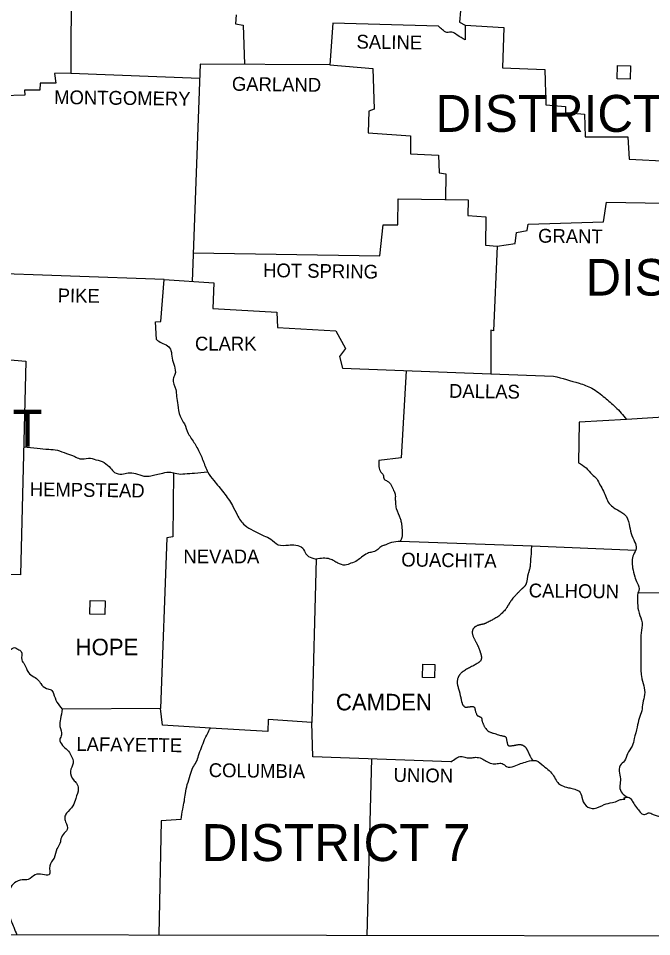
# Model space of a CAD drawing. Extents: x -0.25 to 1.42, y 0 to 0.92.
# Drawn here: x 1.1381 to 1.2274, y 0.5736 to 0.703 of the extents above; entities that cross this region are included whole.
import ezdxf

# ---------------------------------------------------------------- set-up
doc = ezdxf.new("R2010")
doc.units = 0
doc.layers.add('SHET_Annotations', color=7, linetype='Continuous')

msp = doc.modelspace()

# ---------------------------------------------------------------- linework, layer by layer
at = {"layer": 'SHET_Annotations'}
for points in [[(1.17039, 0.73425), (1.17018, 0.72769), (1.15981, 0.72764), (1.15844, 0.72647), (1.15763, 0.72466), (1.15652, 0.72471), (1.15647, 0.7237), (1.15514, 0.72354), (1.15519, 0.72261), (1.14858, 0.72277), (1.14832, 0.72204), (1.1456, 0.72194), (1.14552, 0.69525), (1.14321, 0.6952), (1.14342, 0.69385), (1.14122, 0.69387), (1.14116, 0.69286), (1.13901, 0.69286), (1.13906, 0.69216), (1.1359, 0.69206), (1.13582, 0.68928), (1.13274, 0.68957), (1.13222, 0.66711)], [(1.21552, 0.70884), (1.21225, 0.70923), (1.21238, 0.70798), (1.20639, 0.70775), (1.20621, 0.70599), (1.20058, 0.70567), (1.20027, 0.70246), (1.2011, 0.70204), (1.2011, 0.69994)], [(1.16881, 0.70347), (1.16873, 0.70223), (1.1698, 0.70204), (1.16999, 0.69651)], [(1.19734, 0.70186), (1.18245, 0.7023), (1.18204, 0.69644), (1.16375, 0.69655), (1.16263, 0.66592)], [(1.2011, 0.70204), (1.20654, 0.70171), (1.20634, 0.696), (1.2123, 0.69577), (1.21243, 0.69079), (1.21523, 0.69056), (1.21523, 0.6897), (1.2179, 0.68949), (1.21798, 0.6863), (1.224, 0.6863), (1.22421, 0.68314), (1.22976, 0.68288), (1.22973, 0.67694)], [(1.18204, 0.69644), (1.18808, 0.69592), (1.18826, 0.69017), (1.18751, 0.68993), (1.18741, 0.68687), (1.19337, 0.68643), (1.19337, 0.68392), (1.19734, 0.68371), (1.19742, 0.68122), (1.19835, 0.68106), (1.19832, 0.67745)], [(1.14552, 0.69525), (1.16368, 0.69454)], [(1.16278, 0.66994), (1.18904, 0.66955), (1.18953, 0.67391), (1.19161, 0.67388), (1.19166, 0.67754), (1.20149, 0.67741), (1.20144, 0.6752), (1.20398, 0.67502), (1.20395, 0.67103), (1.20561, 0.67087)], [(1.20561, 0.67087), (1.20815, 0.67126), (1.20833, 0.67282), (1.20984, 0.67308), (1.20994, 0.67398), (1.22057, 0.67432), (1.22099, 0.67707), (1.23188, 0.67691)], [(1.20561, 0.67087), (1.20507, 0.65894), (1.20468, 0.65907), (1.2047, 0.65291)], [(1.15867, 0.6662), (1.13222, 0.66711), (1.11466, 0.66714), (1.11427, 0.66192), (1.11489, 0.66148), (1.11487, 0.65562), (1.10171, 0.65622)], [(1.13222, 0.66711), (1.13222, 0.66104), (1.13323, 0.66086), (1.13312, 0.65521), (1.13919, 0.65471), (1.13844, 0.62458), (1.12604, 0.62486)], [(1.15758, 0.65772), (1.15745, 0.66024), (1.1582, 0.66029), (1.15867, 0.6662), (1.16567, 0.66571), (1.16552, 0.66211), (1.17457, 0.66161), (1.17465, 0.65943), (1.18284, 0.65894), (1.18424, 0.65648), (1.18339, 0.65536), (1.1838, 0.65368), (1.2047, 0.65291)], [(1.19278, 0.65335), (1.19205, 0.64107), (1.18894, 0.64071)], [(1.2047, 0.65291), (1.21355, 0.65259)], [(1.23046, 0.64688), (1.22382, 0.64648)], [(1.22382, 0.64648), (1.21713, 0.64608), (1.21707, 0.64037)], [(1.15999, 0.63897), (1.15989, 0.62992), (1.15906, 0.62982), (1.15815, 0.60578)], [(1.19194, 0.62934), (1.21051, 0.62865), (1.22514, 0.62808)], [(1.18009, 0.62681), (1.1795, 0.60378), (1.17335, 0.60422), (1.1733, 0.60253), (1.16519, 0.603)], [(1.2254, 0.62206), (1.24604, 0.62211)], [(1.12566, 0.61083), (1.12576, 0.5739), (1.29301, 0.57362)], [(1.16519, 0.603), (1.15846, 0.60339), (1.15815, 0.60578), (1.14433, 0.60565)], [(1.19908, 0.59823), (1.17962, 0.59896), (1.1795, 0.60378)], [(1.1879, 0.59865), (1.18721, 0.5738)], [(1.16106, 0.59011), (1.15825, 0.58993), (1.15795, 0.57385)]]:
    msp.add_lwpolyline(points, dxfattribs=at)
for points in [[(1.22249, 0.69447), (1.22255, 0.69636), (1.22439, 0.69631), (1.22434, 0.69442)], [(1.14822, 0.61903), (1.14827, 0.62097), (1.15037, 0.62092), (1.15032, 0.61898)], [(1.19506, 0.61011), (1.19511, 0.612), (1.19679, 0.61195), (1.19674, 0.61006)]]:
    msp.add_lwpolyline(points, close=True, dxfattribs=at)
for points in [[(1.2011, 0.69994), (1.19993, 0.70064), (1.19921, 0.70103), (1.1985, 0.70101), (1.19791, 0.70137), (1.19734, 0.70186)], [(1.15758, 0.65772), (1.15828, 0.65728), (1.15916, 0.65687), (1.15963, 0.65619), (1.15979, 0.65513), (1.16012, 0.65399), (1.1602, 0.65282), (1.15994, 0.65217), (1.1603, 0.65072), (1.16043, 0.64971), (1.16059, 0.64854), (1.16093, 0.64693), (1.16152, 0.64584), (1.16207, 0.64452), (1.16298, 0.64307), (1.16378, 0.64154), (1.16414, 0.64074), (1.16482, 0.63905), (1.16567, 0.63788), (1.16707, 0.63615), (1.16829, 0.63436), (1.16897, 0.63303), (1.17003, 0.63158), (1.17122, 0.63085), (1.17273, 0.6301), (1.17369, 0.62961), (1.17475, 0.62883), (1.17618, 0.62878), (1.17721, 0.62878), (1.1782, 0.62834), (1.17864, 0.62753), (1.17947, 0.62696), (1.18009, 0.62681)], [(1.21355, 0.65259), (1.21713, 0.65158), (1.21894, 0.65088), (1.22076, 0.64955), (1.22226, 0.64823), (1.22382, 0.64648)], [(1.13889, 0.6426), (1.1408, 0.64245), (1.14241, 0.64227), (1.14363, 0.64214), (1.1449, 0.64169), (1.14607, 0.64128), (1.14679, 0.64094), (1.14801, 0.64102), (1.14907, 0.64081), (1.15024, 0.6404), (1.15112, 0.63962), (1.15169, 0.63902), (1.15273, 0.63879), (1.15361, 0.63895), (1.15465, 0.63884), (1.15582, 0.63851), (1.1568, 0.63853), (1.15758, 0.63871), (1.15849, 0.63892), (1.1596, 0.63905), (1.16046, 0.63884), (1.1616, 0.63882), (1.16295, 0.63892), (1.16478, 0.63912)], [(1.18894, 0.64071), (1.18894, 0.63985), (1.18922, 0.63905), (1.18953, 0.63869), (1.18969, 0.63806), (1.1901, 0.6378), (1.19067, 0.63723), (1.19101, 0.63648), (1.19122, 0.63596), (1.19124, 0.63532), (1.19127, 0.63469), (1.19137, 0.63394), (1.19192, 0.63254), (1.19207, 0.632), (1.19215, 0.63153), (1.1922, 0.63075), (1.19218, 0.62984), (1.19194, 0.62934)], [(1.21707, 0.64037), (1.21811, 0.63967), (1.21897, 0.63874), (1.21962, 0.63809), (1.22006, 0.63729), (1.22057, 0.63638), (1.22138, 0.63464), (1.22205, 0.63404), (1.22301, 0.63345), (1.22358, 0.63306), (1.22418, 0.63174), (1.22447, 0.63041), (1.22496, 0.62922), (1.22519, 0.62831), (1.22478, 0.62741), (1.22467, 0.62559), (1.22498, 0.62432), (1.22532, 0.62344), (1.22555, 0.62237), (1.2254, 0.62206)], [(1.18969, 0.62875), (1.18922, 0.62855), (1.18865, 0.62805), (1.18795, 0.62779), (1.18733, 0.62761), (1.18647, 0.62707), (1.18587, 0.6266), (1.18499, 0.62621), (1.18416, 0.62595), (1.18315, 0.62624), (1.18261, 0.62655), (1.18204, 0.62681), (1.18009, 0.62681)], [(1.18969, 0.62875), (1.19075, 0.62919), (1.19194, 0.62934)], [(1.2254, 0.62206), (1.22558, 0.61921), (1.226, 0.61784), (1.22589, 0.61641), (1.22581, 0.61498), (1.22584, 0.61371), (1.22581, 0.61247), (1.22584, 0.6112), (1.22592, 0.61029), (1.22625, 0.60897), (1.22636, 0.60772), (1.2261, 0.60653), (1.22597, 0.60544), (1.22561, 0.60435), (1.2253, 0.60313), (1.22491, 0.60152), (1.22459, 0.60046), (1.22395, 0.59937), (1.22353, 0.59838), (1.22291, 0.59774), (1.22283, 0.59665), (1.22296, 0.59561), (1.22286, 0.5947), (1.22319, 0.59385), (1.224, 0.59325)], [(1.12566, 0.61083), (1.12724, 0.61151), (1.12796, 0.6113), (1.12853, 0.6107), (1.12923, 0.61068), (1.1296, 0.61122), (1.13027, 0.6113), (1.13082, 0.61125), (1.13141, 0.61159), (1.13191, 0.61182), (1.13258, 0.61205), (1.1331, 0.61226), (1.13354, 0.61275), (1.1344, 0.61314), (1.13533, 0.61348), (1.13559, 0.61395), (1.13606, 0.61413), (1.13696, 0.61407), (1.13759, 0.61433), (1.13808, 0.6141), (1.13852, 0.61379), (1.13862, 0.61262), (1.13899, 0.61197), (1.13956, 0.61083), (1.14031, 0.61024), (1.14103, 0.60964), (1.14129, 0.60928), (1.1421, 0.60858), (1.14277, 0.60837), (1.14308, 0.60788), (1.14358, 0.60666), (1.14433, 0.60565)], [(1.14433, 0.60565), (1.14407, 0.6043), (1.14399, 0.60323), (1.14422, 0.60204), (1.14399, 0.60142), (1.14435, 0.60056), (1.14505, 0.59989), (1.14555, 0.59916), (1.14586, 0.59807), (1.14547, 0.59691), (1.14591, 0.59569), (1.14633, 0.59522), (1.14658, 0.59447), (1.14622, 0.59309), (1.14583, 0.59203), (1.14492, 0.59099), (1.14467, 0.59047), (1.1448, 0.5898), (1.14503, 0.58871), (1.14477, 0.58837), (1.1442, 0.5876), (1.14399, 0.58674), (1.14358, 0.58599), (1.14316, 0.58469), (1.14256, 0.58358), (1.14246, 0.58233), (1.14153, 0.58236), (1.14052, 0.58233), (1.13953, 0.58168), (1.13867, 0.58163), (1.13761, 0.58119), (1.13696, 0.58033), (1.13676, 0.57937), (1.13647, 0.57847), (1.13673, 0.57691), (1.13714, 0.57582), (1.13748, 0.57494), (1.13792, 0.57388)], [(1.16106, 0.59011), (1.16129, 0.59156), (1.16152, 0.59273), (1.16168, 0.59379), (1.16194, 0.59504), (1.16235, 0.59636), (1.16272, 0.59745), (1.16321, 0.59823), (1.16352, 0.59914), (1.16393, 0.60025), (1.16438, 0.60137), (1.16519, 0.603)], [(1.19908, 0.59823), (1.19983, 0.59875), (1.2005, 0.59901), (1.2012, 0.59885), (1.2019, 0.5988), (1.20255, 0.59888), (1.20338, 0.59872), (1.20405, 0.59833), (1.20483, 0.598), (1.20561, 0.598), (1.20629, 0.598), (1.20691, 0.59758), (1.20797, 0.59763), (1.2089, 0.598), (1.20981, 0.59828), (1.21106, 0.59841), (1.21212, 0.59766), (1.21292, 0.59701), (1.21355, 0.59628), (1.21401, 0.59545), (1.21453, 0.59499), (1.21534, 0.59468), (1.21598, 0.59452), (1.21674, 0.59431), (1.21715, 0.59411), (1.21751, 0.59328), (1.21811, 0.59206), (1.21928, 0.59167), (1.22065, 0.59221), (1.22182, 0.59252), (1.22265, 0.59278), (1.22312, 0.59296), (1.22358, 0.59304), (1.22348, 0.59312), (1.224, 0.59325), (1.22452, 0.59289), (1.22483, 0.59239), (1.22537, 0.59164), (1.22587, 0.59102), (1.22636, 0.59081), (1.2269, 0.59107), (1.22755, 0.59084), (1.22815, 0.59063), (1.22885, 0.59042), (1.22942, 0.5904), (1.23022, 0.59022), (1.23079, 0.58988), (1.23134, 0.58954), (1.23191, 0.58897), (1.23245, 0.58804), (1.23263, 0.58731), (1.23326, 0.58658), (1.23388, 0.58658), (1.23471, 0.58542), (1.23505, 0.58495), (1.23572, 0.58415), (1.23621, 0.58412), (1.2372, 0.58397)]]:
    msp.add_spline(points, degree=3, dxfattribs=at)
msp.add_open_spline([(1.21045, 0.62865), (1.21038, 0.62772), (1.2103, 0.62678), (1.21023, 0.62585), (1.21021, 0.62561), (1.21015, 0.62538), (1.21009, 0.62514), (1.21005, 0.62503), (1.21002, 0.62491), (1.20998, 0.6248), (1.20995, 0.62468), (1.20992, 0.62457), (1.20989, 0.62445), (1.20984, 0.62423), (1.20982, 0.62401), (1.20978, 0.62379), (1.20976, 0.62368), (1.20974, 0.62357), (1.20971, 0.62346), (1.20969, 0.62341), (1.20967, 0.62336), (1.20965, 0.62331), (1.20964, 0.62328), (1.20963, 0.62325), (1.20962, 0.62323), (1.20961, 0.6232), (1.20959, 0.62318), (1.20958, 0.62315), (1.20954, 0.62308), (1.20949, 0.62301), (1.20943, 0.62294), (1.20937, 0.62288), (1.20931, 0.62282), (1.20925, 0.62277), (1.20919, 0.62271), (1.20912, 0.62266), (1.20906, 0.6226), (1.209, 0.62254), (1.20894, 0.62249), (1.20888, 0.62243), (1.20876, 0.6223), (1.20864, 0.62218), (1.20852, 0.62205), (1.20839, 0.62192), (1.20827, 0.6218), (1.20815, 0.62167), (1.20791, 0.62143), (1.20771, 0.62115), (1.2075, 0.62087), (1.20745, 0.62079), (1.20739, 0.62071), (1.20734, 0.62063), (1.20729, 0.62054), (1.20724, 0.62046), (1.20719, 0.62038), (1.20714, 0.62029), (1.20709, 0.62021), (1.20704, 0.62013), (1.20699, 0.62004), (1.20694, 0.61996), (1.20688, 0.61988), (1.20671, 0.61964), (1.2065, 0.61942), (1.20629, 0.61921), (1.20605, 0.61898), (1.20581, 0.61876), (1.20553, 0.61859), (1.20527, 0.61843), (1.205, 0.61829), (1.20473, 0.61815), (1.20445, 0.618), (1.20418, 0.61786), (1.2039, 0.61773), (1.20382, 0.6177), (1.20374, 0.61767), (1.20366, 0.61765), (1.20358, 0.61763), (1.2035, 0.61761), (1.20341, 0.61759), (1.20333, 0.61758), (1.20325, 0.61756), (1.20316, 0.61754), (1.20308, 0.61753), (1.203, 0.6175), (1.20291, 0.61747), (1.20278, 0.61743), (1.20266, 0.61737), (1.20254, 0.61729), (1.20248, 0.61726), (1.20243, 0.61722), (1.20238, 0.61717), (1.20236, 0.61714), (1.20233, 0.61712), (1.20231, 0.61709), (1.20228, 0.61706), (1.20226, 0.61704), (1.20224, 0.61701), (1.20218, 0.61692), (1.20215, 0.61683), (1.20212, 0.61674), (1.20209, 0.61664), (1.20208, 0.61654), (1.20208, 0.61645), (1.2021, 0.61626), (1.20214, 0.61607), (1.20221, 0.61589), (1.20227, 0.61576), (1.20233, 0.61563), (1.20239, 0.61551), (1.20246, 0.61538), (1.20253, 0.61526), (1.20259, 0.61513), (1.20266, 0.615), (1.20273, 0.61488), (1.20279, 0.61475), (1.20286, 0.61462), (1.20291, 0.61449), (1.20297, 0.61436), (1.20306, 0.61412), (1.20314, 0.61388), (1.20322, 0.61363), (1.20325, 0.61356), (1.20327, 0.61349), (1.20329, 0.61341), (1.20331, 0.61334), (1.20333, 0.61326), (1.20334, 0.61318), (1.20336, 0.61311), (1.20337, 0.61303), (1.20337, 0.61295), (1.20337, 0.61291), (1.20337, 0.61288), (1.20337, 0.61284), (1.20337, 0.6128), (1.20336, 0.61276), (1.20335, 0.61273), (1.20334, 0.61263), (1.20329, 0.61253), (1.20323, 0.61245), (1.20316, 0.61236), (1.20308, 0.61229), (1.20299, 0.61223), (1.20276, 0.61209), (1.20253, 0.61195), (1.20229, 0.61182), (1.202, 0.61166), (1.2017, 0.61151), (1.20141, 0.61135), (1.20115, 0.61121), (1.2009, 0.61104), (1.20066, 0.61086), (1.20053, 0.61076), (1.20042, 0.61065), (1.20032, 0.61052), (1.20027, 0.61046), (1.20023, 0.6104), (1.20019, 0.61033), (1.20015, 0.61026), (1.20012, 0.61018), (1.20009, 0.61011), (1.20002, 0.60993), (1.19998, 0.60975), (1.19997, 0.60957), (1.19996, 0.6094), (1.19997, 0.60922), (1.20001, 0.60904), (1.20003, 0.60894), (1.20006, 0.60884), (1.20009, 0.60874), (1.20012, 0.60864), (1.20015, 0.60854), (1.20018, 0.60843), (1.20021, 0.60833), (1.20024, 0.60823), (1.20027, 0.60813), (1.2003, 0.60803), (1.20032, 0.60793), (1.20035, 0.60782), (1.2004, 0.60758), (1.20045, 0.60732), (1.2005, 0.60707), (1.20053, 0.60697), (1.20055, 0.60686), (1.20058, 0.60675), (1.2006, 0.60664), (1.20064, 0.60654), (1.20068, 0.60643), (1.20072, 0.60633), (1.20077, 0.60624), (1.20084, 0.60616), (1.20088, 0.60611), (1.20091, 0.60608), (1.20096, 0.60604), (1.20098, 0.60603), (1.201, 0.60601), (1.20102, 0.606), (1.20105, 0.60598), (1.20107, 0.60597), (1.2011, 0.60596), (1.20113, 0.60594), (1.20117, 0.60593), (1.20121, 0.60593), (1.20125, 0.60593), (1.20128, 0.60594), (1.20132, 0.60595), (1.20136, 0.60595), (1.20139, 0.60596), (1.20143, 0.60597), (1.20147, 0.60598), (1.2015, 0.60598), (1.20154, 0.60598), (1.20157, 0.60599), (1.20161, 0.60599), (1.20164, 0.60599), (1.20168, 0.606), (1.20171, 0.606), (1.20175, 0.60601), (1.20182, 0.60602), (1.20189, 0.60603), (1.20195, 0.60604), (1.20202, 0.60605), (1.20209, 0.60605), (1.20216, 0.60603), (1.2022, 0.60603), (1.20223, 0.60602), (1.20227, 0.606), (1.20228, 0.60599), (1.2023, 0.60598), (1.20232, 0.60597), (1.20234, 0.60596), (1.20235, 0.60595), (1.20237, 0.60593), (1.2024, 0.6059), (1.20242, 0.60586), (1.20243, 0.60582), (1.20244, 0.60578), (1.20244, 0.60574), (1.20245, 0.6057), (1.20246, 0.60563), (1.20248, 0.60556), (1.2025, 0.60549), (1.20255, 0.60529), (1.20262, 0.60509), (1.20271, 0.60489), (1.20273, 0.60483), (1.20278, 0.60477), (1.20284, 0.60474), (1.20291, 0.60471), (1.20298, 0.60468), (1.20304, 0.60465), (1.20311, 0.60461), (1.20318, 0.60458), (1.20324, 0.60455), (1.2033, 0.60452), (1.20335, 0.60446), (1.20338, 0.6044), (1.2034, 0.60436), (1.20341, 0.60433), (1.20342, 0.60429), (1.20342, 0.60425), (1.20343, 0.60421), (1.20343, 0.60417), (1.20344, 0.60413), (1.20345, 0.60409), (1.20345, 0.60405), (1.20346, 0.60401), (1.20347, 0.60397), (1.20348, 0.60393), (1.20354, 0.60378), (1.2036, 0.60363), (1.20366, 0.60349), (1.20373, 0.60333), (1.20381, 0.60319), (1.2039, 0.60305), (1.20406, 0.6028), (1.20427, 0.60257), (1.20455, 0.60246), (1.20472, 0.60238), (1.20489, 0.60233), (1.20507, 0.60227), (1.20541, 0.60217), (1.20576, 0.60206), (1.2061, 0.60196), (1.20628, 0.60191), (1.20647, 0.60188), (1.20665, 0.60183), (1.20668, 0.60183), (1.2067, 0.60182), (1.20673, 0.6018), (1.2068, 0.60174), (1.20686, 0.60166), (1.20688, 0.60158), (1.2069, 0.60143), (1.20693, 0.60128), (1.20696, 0.60114), (1.20698, 0.601), (1.20701, 0.60086), (1.20704, 0.60072), (1.20705, 0.60066), (1.20708, 0.60062), (1.20713, 0.60057), (1.20717, 0.60054), (1.20722, 0.60052), (1.20727, 0.60051), (1.20739, 0.6005), (1.20751, 0.6005), (1.20763, 0.60052), (1.20775, 0.60053), (1.20788, 0.60054), (1.208, 0.60056), (1.20808, 0.60058), (1.20817, 0.6006), (1.20826, 0.60062), (1.20834, 0.60064), (1.20843, 0.60065), (1.20852, 0.60067), (1.20867, 0.60069), (1.20883, 0.60068), (1.20899, 0.60065), (1.20907, 0.60063), (1.20914, 0.60061), (1.20922, 0.60057), (1.20926, 0.60055), (1.2093, 0.60053), (1.20933, 0.60051), (1.20937, 0.60049), (1.20941, 0.60046), (1.20945, 0.60043), (1.20954, 0.60036), (1.20962, 0.60028), (1.20968, 0.60018), (1.20974, 0.60008), (1.20979, 0.59999), (1.20984, 0.59989), (1.20988, 0.59981), (1.20992, 0.59974), (1.20995, 0.59966), (1.20999, 0.59958), (1.21002, 0.5995), (1.21006, 0.59942), (1.21009, 0.59934), (1.21013, 0.59927), (1.21016, 0.59919), (1.2102, 0.59911), (1.21024, 0.59903), (1.21028, 0.59896), (1.21037, 0.59879), (1.21044, 0.59862), (1.21056, 0.59848)], degree=3, dxfattribs=at)

# ---------------------------------------------------------------- texts
for s, rotation, p in [('SALINE', 359.1885, (1.18576, 0.69873)), ('GARLAND', 359.2717, (1.16821, 0.69279)), ('MONTGOMERY', 359.2707, (1.14317, 0.69092)), ('GRANT', 359.3139, (1.21135, 0.67139)), ('HOT SPRING', 359.1956, (1.17261, 0.66654)), ('PIKE', 359.1737, (1.14367, 0.66299)), ('DALLAS', 359.2802, (1.1988, 0.64953)), ('HEMPSTEAD', 359.2571, (1.13973, 0.63568)), ('OUACHITA', 359.2027, (1.19207, 0.62577)), ('CALHOUN', 359.2686, (1.21003, 0.62142)), ('LAFAYETTE', 359.2511, (1.1463, 0.59979)), ('COLUMBIA', 359.2105, (1.16495, 0.59611)), ('UNION', 359.2015, (1.19099, 0.59543))]:
    msp.add_text(s, height=0.001945, rotation=rotation, dxfattribs=at).set_placement(p)
for s, height, p in [('DISTRICT 6', 0.005203, (1.1969, 0.68699)), ('DISTRICT 2', 0.005157, (1.21806, 0.66393)), ('CLARK', 0.001945, (1.16302, 0.65619)), ('DISTRICT', 0.005203, (1.10947, 0.64263)), ('NEVADA', 0.001945, (1.16139, 0.62621)), ('HOPE', 0.002334, (1.1462, 0.61325)), ('CAMDEN', 0.002334, (1.18287, 0.60549)), ('DISTRICT 7', 0.005203, (1.16397, 0.58426))]:
    msp.add_text(s, height=height, dxfattribs=at).set_placement(p)

doc.saveas('drawing.dxf')
